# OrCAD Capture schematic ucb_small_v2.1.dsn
size C; title: NCREPT Small UCB; rev: 2.1; company: University of Arkansas (NCREPT); note: 700 W. Research Center Blvd; note: Fayetteville, AR 72701
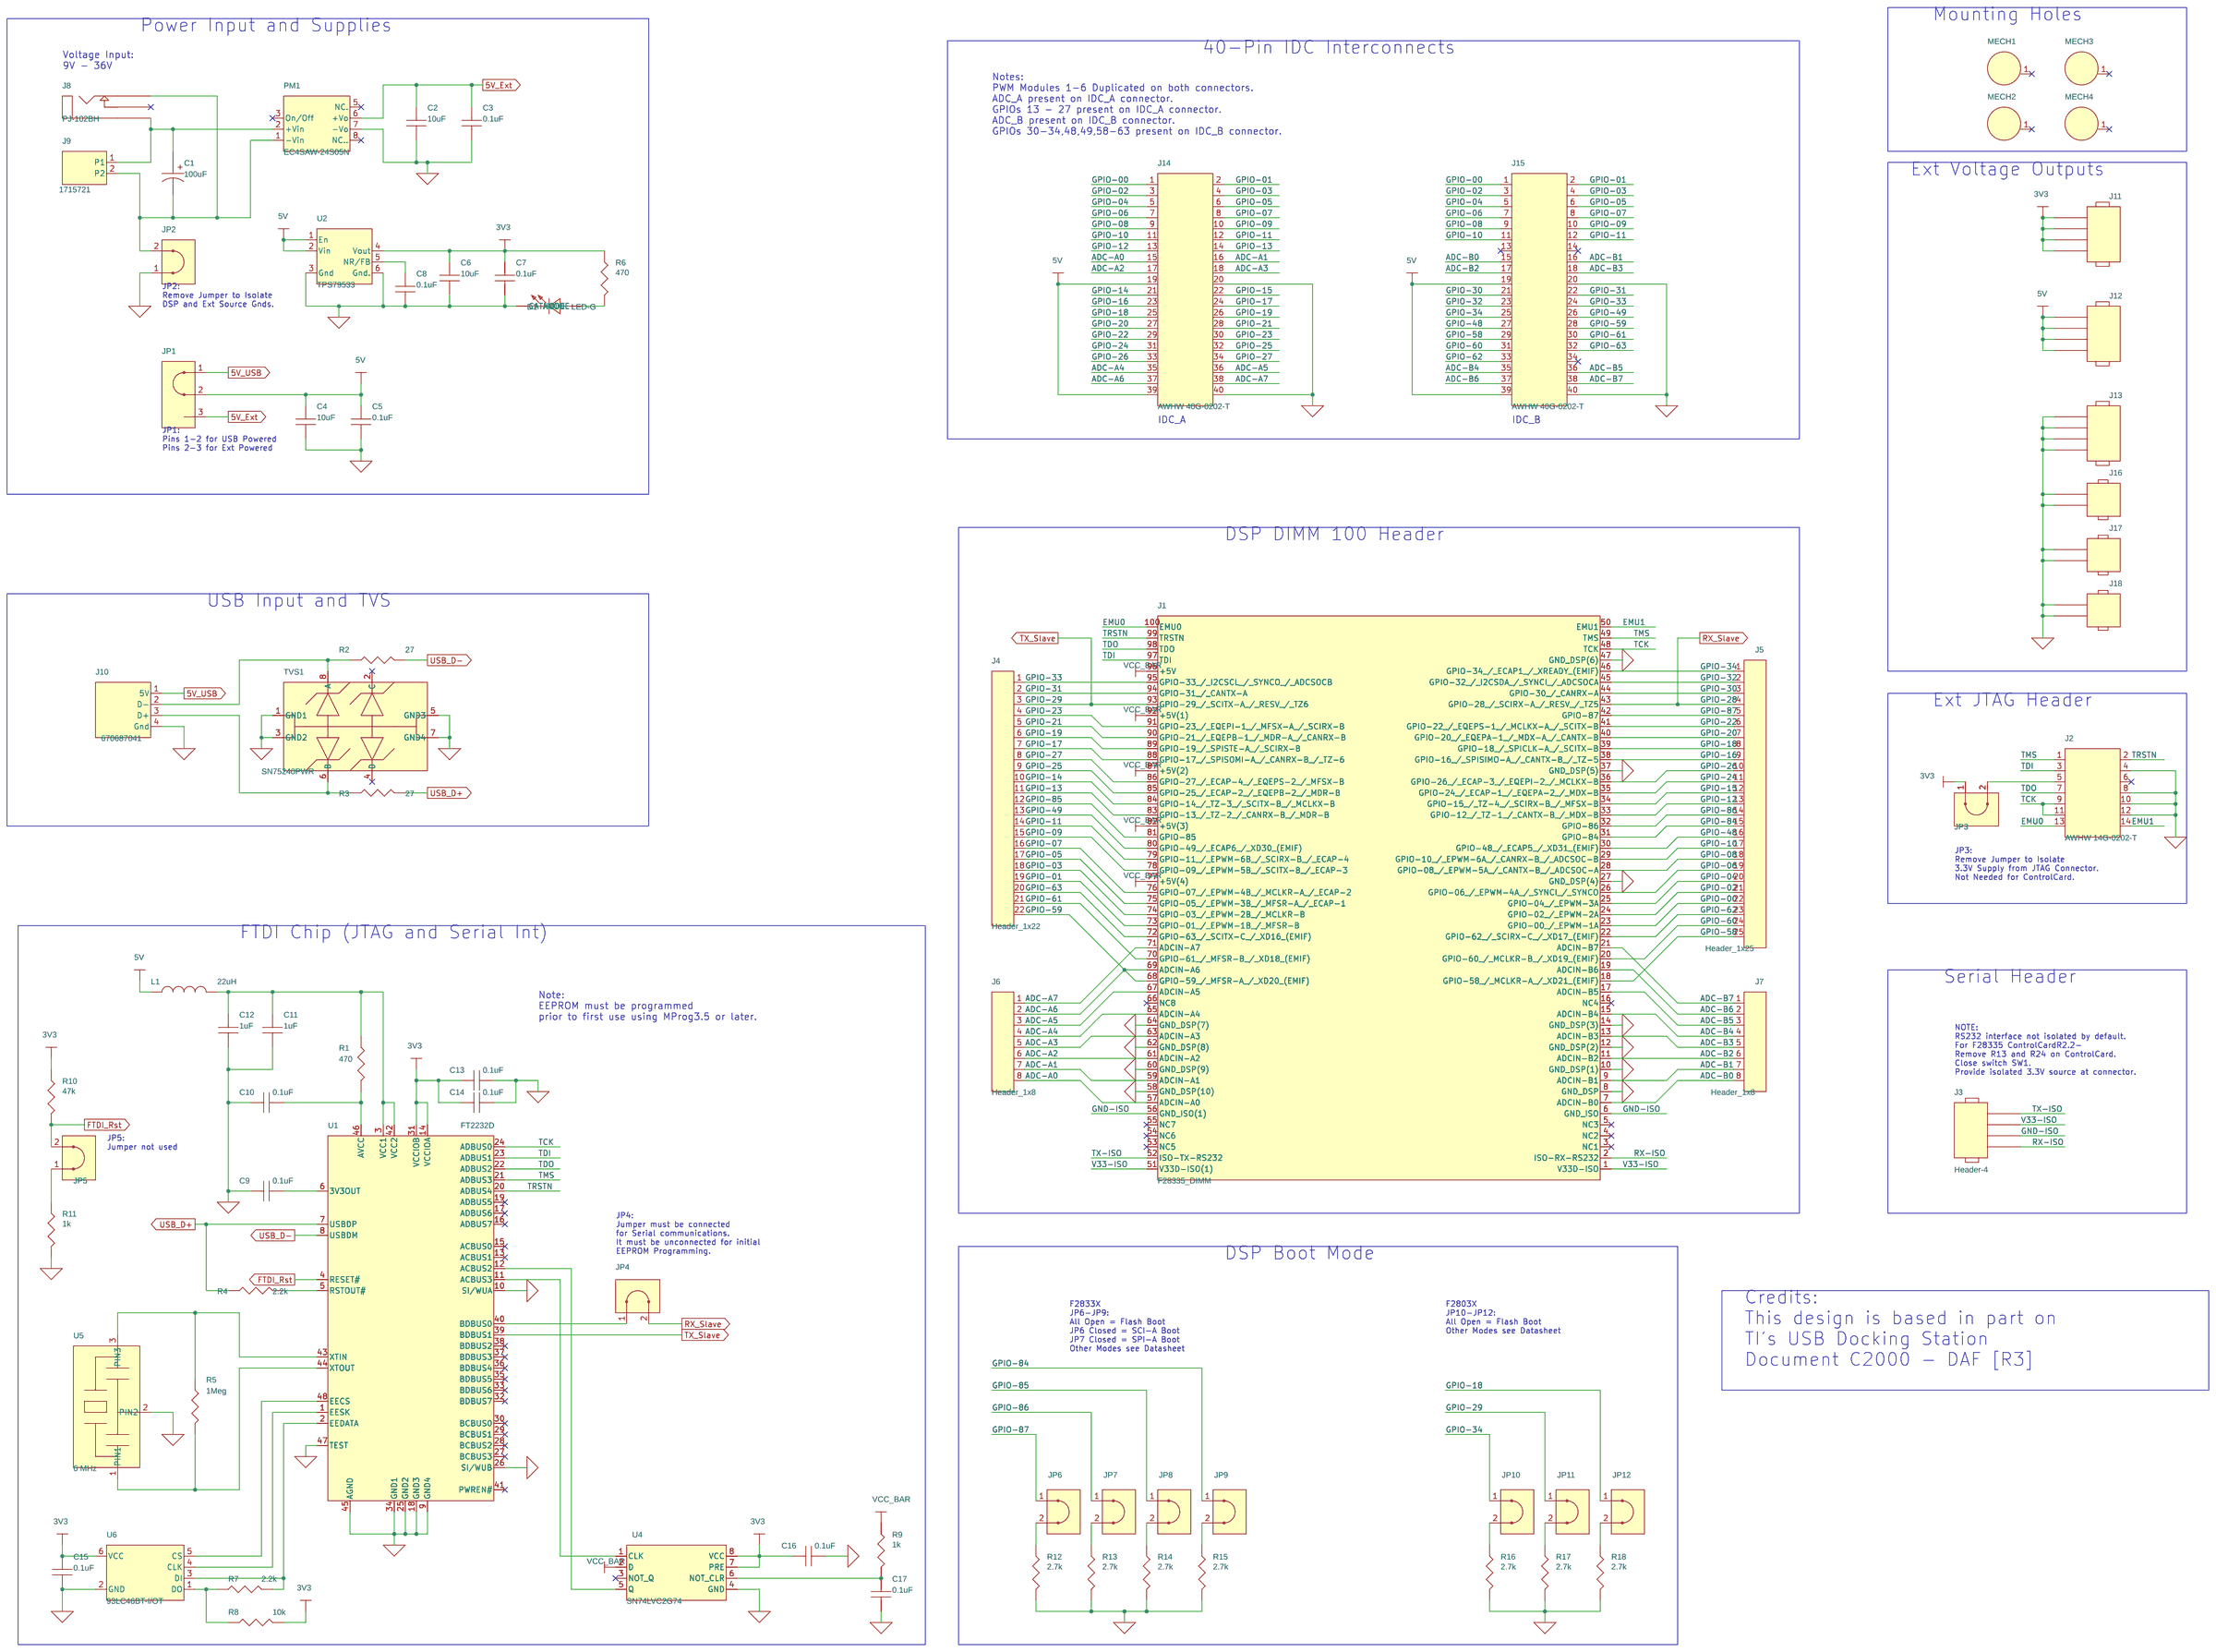
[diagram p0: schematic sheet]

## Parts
C1  100uF  [UVZ1H101MPD]
C2  10uF  [C_1206]
C3  0.1uF  [C_0603]
C4  10uF  [C_1206]
C5  0.1uF  [C_0603]
C6  10uF  [C_1206]
C7  0.1uF  [C_0603]
C8  0.1uF  [C_0603]
C9  0.1uF  [C_0603]
C10  0.1uF  [C_0603]
C11  1uF  [C_0603]
C12  1uF  [C_0603]
C13  0.1uF  [C_0603]
C14  0.1uF  [C_0603]
C15  0.1uF  [C_0603]
C16  0.1uF  [C_0603]
C17  0.1uF  [C_0603]
D1  LED-G  [LED_0805-GREEN]
J1  F28335_DIMM  [5390213-1]
J2  AWHW 14G-0202-T  [14-IDC-M]
J3  Header-4  [H_1x4]
J4  Header_1x22  [H_1X22]
J5  Header_1x25  [H_1X25]
J6  Header_1x8  [H_1X8]
J7  Header_1x8  [H_1X8]
J8  PJ-102BH  [DC-PWR_JACK]
J9  1715721  [1715721]
J10  670687041  [USB-B_TH]
J11  Header-4  [H_1x4]
J12  Header-4  [H_1x4]
J13  Header-4  [H_1x4]
J14  AWHW 40G-0202-T  [40-IDC-M_MNT]
J15  AWHW 40G-0202-T  [40-IDC-M_MNT]
J16  Header-2  [H_1x2]
J17  Header-2  [H_1x2]
J18  Header-2  [H_1x2]
JP1  JP3  [J_1X3]
JP2  JP2  [J_1X2]
JP3  JP2  [J_1X2]
JP4  JP2  [J_1X2]
JP5  JP2  [J_1X2]
JP6  JP2  [J_1X2]
JP7  JP2  [J_1X2]
JP8  JP2  [J_1X2]
JP9  JP2  [J_1X2]
JP10  JP2  [J_1X2]
JP11  JP2  [J_1X2]
JP12  JP2  [J_1X2]
L1  22uH  [L_0805]
MECH1  Mech_Hole  [4-40_SCREW]
MECH2  Mech_Hole  [4-40_SCREW]
MECH3  Mech_Hole  [4-40_SCREW]
MECH4  Mech_Hole  [4-40_SCREW]
PM1  EC4SAW-24S05N  [SIP-8]
R1  470  [R_0805]
R2  27  [R_0805]
R3  27  [R_0805]
R4  2.2k  [R_0805]
R5  1Meg  [R_0805]
R6  470  [R_0805]
R7  2.2k  [R_0805]
R8  10k  [R_0805]
R9  1k  [R_0805]
R10  47k  [R_0805]
R11  1k  [R_0805]
R12  2.7k  [R_0805]
R13  2.7k  [R_0805]
R14  2.7k  [R_0805]
R15  2.7k  [R_0805]
R16  2.7k  [R_0805]
R17  2.7k  [R_0805]
R18  2.7k  [R_0805]
TVS1  SN75240PWR  [8-TSSOP]
U1  FT2232D  [LQFP-48]
U2  TPS79533  [SOT-223-6]
U4  SN74LVC2G74  [8-VSSOP]
U5  6 MHz  [CSTCR]
U6  93LC46BT-I/OT  [SOT-23-6]

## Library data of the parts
C1 = CAP_P: Electrolytic Capacitor (50V/100uF); Manufacturer: Nichicon; Part_Number: TMP-145; Voltage: 50V; Datasheet: Nicicon-e-uvz-880014.pdf
C2 C4 C6 = CAP_NP: 10µF ±20% 35V X7R MLCC; Manufacturer: TDK; Manufacturer_Part_Number: C3216X7R1V106M160AC; Part_Number: TMP-2; Tolerance: 20%; Voltage: 35V; Datasheet: TDK-mlcc_commercial_general_en.pdf
C3 C5 C7-C10 C13-C17 = CAP_NP: 0.1µF ±10% 50V X7R MLCC; Manufacturer: TDK; Manufacturer_Part_Number: C1608X7R1H104K080AA; Part_Number: TMP-1; Tolerance: 10%; Voltage: 50V; Datasheet: TDK-mlcc_commercial_general_en.pdf
C11 C12 = CAP_NP: 1µF ±10% 35V X7R MLCC; Manufacturer: TDK; Manufacturer_Part_Number: C1608X7R1V105K080AC; Part_Number: TMP-8; Tolerance: 10%; Voltage: 35V; Datasheet: TDK-mlcc_commercial_general_en.pdf
D1 = LED: LED, 0805, Green, VF= 2.2V; Manufacturer: OSRAM; Manufacturer_Part_Number: LG R971-KN-1; Part_Number: TMP-132; STEP_Model: LED_0805-Green.stp; Datasheet: OSRAM-LGR971-CHIPLED-0805-318376.pdf
J1 = F28335_DIMM: DIMM 100 connector for TI F28335 DSP; Manufacturer: AMP; Part_Number: TMP-170; STEP_Model: c-5390213-01-b-3d.stp; Datasheet: AMP-NG_CD_5390213_B2-667800.pdf
J2 = Header_2x7: 14-POS Header, Shrouded, 0.100", TH; Manufacturer: Assmann; Part_Number: TMP-124; STEP_Model: HDB-14.stp; User_Field1: SBH11-PBPC-D07-ST-BK; Datasheet: Assmann-AWHW-xxG-0x02-T.pdf
J3 J11-J13 = HEADER_4: Male, TH, Straight, 4-Pos, 0.1" Pitch; Manufacturer: Various; Manufacturer_Part_Number: PRT-00116; Part_Number: TMP-25; STEP_Model: Pin Header 1x4 TH Pitch 2.54mm.stp
J4 = Header_1x22: Male, TH, Straight, 22-Pos, 0.1" Pitch; Manufacturer: Various; Manufacturer_Part_Number: PRT-00116; Part_Number: TMP-168; STEP_Model: mill-max-800-10-022-10-002000.stp; Datasheet: Sullins-z RzCzzzSzzN-RC, ST,11635-B.pdf
J5 = Header_1x25: Male, TH, Straight, 25-Pos, 0.1" Pitch; Manufacturer: Various; Manufacturer_Part_Number: PRT-00116; Part_Number: TMP-169; STEP_Model: mill-max-800-10-025-10-002000.stp; Datasheet: Sullins-z RzCzzzSzzN-RC, ST,11635-B.pdf
J6 J7 = Header_1x8: Male, TH, Straight, 8-Pos, 0.1" Pitch; Manufacturer: Various; Manufacturer_Part_Number: PRT-00116; Part_Number: TMP-167; STEP_Model: Pin Header 1x8 TH Pitch 2.54mm.stp; Datasheet: Sullins-z RzCzzzSzzN-RC, ST,11635-B.pdf
J8 = DC-Jack_3: DC Power Jack, 2.5mm Center Pin, TH; Manufacturer: CUI; Part_Number: TMP-150; STEP_Model: pj-102bh.stp; Datasheet: CUI-PJ-102BH-524153.pdf
J9 = Connector-2: PCB Terminal Block, 2-position, 90 degrees, 5.08mm; Manufacturer: Phoenix Contact; Part_Number: TMP-111; Rating: 17.5A; STEP_Model: 1715721.stp; Voltage: 400V; Datasheet: PhoenixContact-1715734.pdf
J10 = USB-B: USB - B Receptacle Connector 4-POS, TH, Right Angle; Manufacturer: Molex; Part_Number: TMP-161; STEP_Model: USB-0670687041.stp; Datasheet: Molex-670687041_sd.pdf
J14 J15 = Header_2x20: 40-POS Header, Shrouded, 0.100", TH, Male w/ Mounting; Manufacturer: Assmann; Part_Number: TMP-162; STEP_Model: HDB-40.stp; Datasheet: Assmann-AWHW-xxG-0x02-T.pdf
J16-J18 = HEADER_2: Male, TH, Straight, 2-Pos, 0.1" Pitch; Manufacturer: Various; Manufacturer_Part_Number: PRT-00116; Part_Number: TMP-101; STEP_Model: Pin Header 1x2 TH Pitch 2.54mm.stp
JP1 = JP3: Male, TH, Straight, 3-Pos, 0.1" Pitch; Manufacturer: Various; Manufacturer_Part_Number: PRT-00116; Part_Number: TMP-136
JP2-JP12 = JP2: Male, TH, Straight, 2-Pos, 0.1" Pitch; Manufacturer: Various; Manufacturer_Part_Number: PRT-00116; Part_Number: TMP-135
L1 = Ind: 22uH,13mA, Fixed Inductor, ±30%; Manufacturer: Murata; Manufacturer_Part_Number: LQM21FN220N00L; Part_Number: TMP-159; Rating: 13mA; Tolerance: 30.00%; Datasheet: Murata-o05e.pdf
MECH1-MECH4 = Mech_Hole: Mounting Hole for 4-40 Screw, 0.125"; Part_Number: TMP-103
PM1 = EC4SA: Isolated DC/DC Converters 6 Watt, 9-36 Vin, 5 Vout; Manufacturer: Cincon; Part_Number: TMP-118; STEP_Model: PwrMod-SIP8.stp; Datasheet: CINCON-EC4SAW V10-557886.pdf
R1 R6 = R-Standard: 470 Ohm, 1%, 0805; Manufacturer: KOA Speer; Manufacturer_Part_Number: RK73H2ATTD4700F; Part_Number: TMP-172; Rating: 0.125W; Tolerance: 1%; Datasheet: KOA-RK73H-5715.pdf
R2 R3 = R-Standard: 27 Ohm, 1%, 0805; Manufacturer: KOA Speer; Manufacturer_Part_Number: RK73H2ATTD27R0F; Part_Number: TMP-171; Rating: 0.125W; Tolerance: 1%; Datasheet: KOA-RK73H-5715.pdf
R4 R7 = R-Standard: 2.2k Ohm, 1%, 0805; Manufacturer: KOA Speer; Manufacturer_Part_Number: RK73H2ATTD2201F; Part_Number: TMP-173; Rating: 0.125W; Tolerance: 1%; Datasheet: KOA-RK73H-5715.pdf
R5 = R-Standard: 1Meg Ohm, 1%, 0805; Manufacturer: KOA Speer; Manufacturer_Part_Number: RK73H2ATTD1004F; Part_Number: TMP-175; Rating: 0.125W; Tolerance: 1%; Datasheet: KOA-RK73H-5715.pdf
R8 = R-Standard: 10k Ohm, 1%, 0805; Manufacturer: KOA Speer; Manufacturer_Part_Number: RK73H2ATTD1002F; Part_Number: TMP-68; Rating: 0.125W; Tolerance: 1%; Datasheet: KOA-RK73H-5715.pdf
R9 R11 = R-Standard: 1k Ohm, 1%, 0805; Manufacturer: KOA Speer; Manufacturer_Part_Number: RK73H2ATTD1001F; Part_Number: TMP-48; Rating: 0.125W; Tolerance: 1%; Datasheet: KOA-RK73H-5715.pdf
R10 = R-Standard: 47k Ohm, 1%, 0805; Manufacturer: KOA Speer; Manufacturer_Part_Number: RK73H2ATTD4702F; Part_Number: TMP-140; Rating: 0.125W; Tolerance: 1%; Datasheet: KOA-RK73H-5715.pdf
R12-R18 = R-Standard: 2.7k Ohm, 1%, 0805; Manufacturer: KOA Speer; Manufacturer_Part_Number: RK73H2ATTD2701F; Part_Number: TMP-174; Rating: 0.125W; Tolerance: 1%; Datasheet: KOA-RK73H-5715.pdf
TVS1 = SN75240: TVS Diode Arrays Dual USB Port; Manufacturer: TI; Part_Number: TMP-166; STEP_Model: TSSOP65P640X120-8N.stp; Datasheet: TI-sn75240-557324.pdf
U1 = FT2232D: USB Interface IC USB to Dual UART/ FIFO/SPI/JTAG/I2C (TI); Manufacturer: FTDI; Manufacturer_Part_Number: FT2232D-REEL; Part_Number: TMP-158; STEP_Model: LQFP-48.stp; Datasheet: FTDI-DS_FT2232D-17197.pdf
U2 = TPS795: LDO Voltage Reg, 3.3V, 500mA, 2%; Manufacturer: TI; Manufacturer_Part_Number: TPS79533DCQR; Part_Number: TMP-155; STEP_Model: SOT-223-6.stp; Datasheet: TI-tps795-706600.pdf
U4 = SN74LVC2G74: Flip Flops Single Pos Edge Trig; Manufacturer: TI; Part_Number: TMP-157; STEP_Model: VSSOP_SOP50P310X90-8N.stp; Datasheet: TI-sn74lvc2g74-556136.pdf
U5 = CSTCR_G: 6MHz Ceramic Resonator Built in Capacitor 15pF ±0.2%; Manufacturer: Murata; Manufacturer_Part_Number: CSTCR6M00G53Z-R0; Part_Number: TMP-160; Datasheet: Murata-p16e.pdf
U6 = 93LC46BT: EEPROM 64x16, 1kb, Serial, 3-Wire, Microwire; Manufacturer: Microchip; Part_Number: TMP-156; STEP_Model: SOT23-6.stp; Datasheet: Microchip-21749d-6388.pdf

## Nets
3V3: C6.1 C7.1 C13.1 C14.1 C15.1 C16.1 J11.1 J11.2 J11.3 J11.4 JP3.1 R6.1 R8.2 R9.1 R10.1 U1.14(VCCIOA) U1.31(VCCIOB) U2.4(Vout) U4.2(D) U4.7(PRE) U4.8(VCC) U6.6(VCC)
5V: C4.1 C5.1 J1.77(+5V(4)) J1.82(+5V(3)) J1.87(+5V(2)) J1.92(+5V(1)) J1.96(+5V) J12.1 J12.2 J12.3 J12.4 J14.19 J14.39 J15.19 J15.39 JP1.2 L1.1 U2.1(En) U2.2(Vin)
5V_Ext: C2.1 C3.1 JP1.3 PM1.6(+Vo)
5V_USB: J10.1(5V) JP1.1
GND-ISO: J1.6(GND_ISO) J1.56(GND_ISO(1)) J3.3
GND_SIGNAL: C2.2 C3.2 C4.2 C5.2 C6.2 C7.2 C8.2 C9.1 C10.1 C11.2 C12.2 C13.2 C14.2 C15.2 C16.2 C17.2 D1.1(CATHODE) J1.8(GND_DSP) J1.10(GND_DSP(1)) J1.12(GND_DSP(2)) J1.14(GND_DSP(3)) J1.27(GND_DSP(4)) J1.37(GND_DSP(5)) J1.47(GND_DSP(6)) J1.58(GND_DSP(10)) J1.60(GND_DSP(9)) J1.62(GND_DSP(8)) J1.64(GND_DSP(7)) J2.4 J2.8 J2.10 J2.12 J10.4(Gnd) J13.1 J13.2 J13.3 J13.4 J14.20 J14.40 J15.20 J15.40 J16.1 J16.2 J17.1 J17.2 J18.1 J18.2 JP2.1 PM1.7(-Vo) R11.2 R12.2 R13.2 R14.2 R15.2 R16.2 R17.2 R18.2 TVS1.1(GND1) TVS1.3(GND2) TVS1.5(GND3) TVS1.7(GND4) U1.9(GND4) U1.10(SI/WUA) U1.18(GND3) U1.25(GND2) U1.26(SI/WUB) U1.34(GND1) U1.45(AGND) U1.47(TEST) U2.3(Gnd) U2.6(Gnd.) U4.4(GND) U5.2(PIN2) U6.2(GND)
V33-ISO: J1.1(V33D-ISO) J1.51(V33D-ISO(1)) J3.2
ADC-A0: J1.57(ADCIN-A0) J6.8 J14.15
ADC-A1: J1.59(ADCIN-A1) J6.7 J14.16
ADC-A2: J1.61(ADCIN-A2) J6.6 J14.17
ADC-A3: J1.63(ADCIN-A3) J6.5 J14.18
ADC-A4: J1.65(ADCIN-A4) J6.4 J14.35
ADC-A5: J1.67(ADCIN-A5) J6.3 J14.36
ADC-A6: J1.69(ADCIN-A6) J6.2 J14.37
ADC-A7: J1.71(ADCIN-A7) J6.1 J14.38
ADC-B0: J1.7(ADCIN-B0) J7.8 J15.15
ADC-B1: J1.9(ADCIN-B1) J7.7 J15.16
ADC-B2: J1.11(ADCIN-B2) J7.6 J15.17
ADC-B3: J1.13(ADCIN-B3) J7.5 J15.18
ADC-B4: J1.15(ADCIN-B4) J7.4 J15.35
ADC-B5: J1.17(ADCIN-B5) J7.3 J15.36
ADC-B6: J1.19(ADCIN-B6) J7.2 J15.37
ADC-B7: J1.21(ADCIN-B7) J7.1 J15.38
EMU0: J1.100(EMU0) J2.13
EMU1: J1.50(EMU1) J2.14
FTDI_Rst: JP5.2 R10.2 U1.4(RESET#)
GPIO-00: J1.23(GPIO-00_/_EPWM-1A) J5.22 J14.1 J15.1
GPIO-01: J1.73(GPIO-01_/_EPWM-1B_/_MFSR-B) J4.19 J14.2 J15.2
GPIO-02: J1.24(GPIO-02_/_EPWM-2A) J5.21 J14.3 J15.3
GPIO-03: J1.74(GPIO-03_/_EPWM-2B_/_MCLKR-B) J4.18 J14.4 J15.4
GPIO-04: J1.25(GPIO-04_/_EPWM-3A) J5.20 J14.5 J15.5
GPIO-05: J1.75(GPIO-05_/_EPWM-3B_/_MFSR-A_/_ECAP-1) J4.17 J14.6 J15.6
GPIO-06: J1.26(GPIO-06_/_EPWM-4A_/_SYNCI_/_SYNCO) J5.19 J14.7 J15.7
GPIO-07: J1.76(GPIO-07_/_EPWM-4B_/_MCLKR-A_/_ECAP-2) J4.16 J14.8 J15.8
GPIO-08: J1.28(GPIO-08_/_EPWM-5A_/_CANTX-B_/_ADCSOC-A) J5.18 J14.9 J15.9
GPIO-09: J1.78(GPIO-09_/_EPWM-5B_/_SCITX-B_/_ECAP-3) J4.15 J14.10 J15.10
GPIO-10: J1.29(GPIO-10_/_EPWM-6A_/_CANRX-B_/_ADCSOC-B) J5.17 J14.11 J15.11
GPIO-11: J1.79(GPIO-11_/_EPWM-6B_/_SCIRX-B_/_ECAP-4) J4.14 J14.12 J15.12
GPIO-12: J1.33(GPIO-12_/_TZ-1_/_CANTX-B_/_MDX-B) J5.13 J14.13
GPIO-13: J1.83(GPIO-13_/_TZ-2_/_CANRX-B_/_MDR-B) J4.11 J14.14
GPIO-14: J1.84(GPIO-14_/_TZ-3_/_SCITX-B_/_MCLKX-B) J4.10 J14.21
GPIO-15: J1.34(GPIO-15_/_TZ-4_/_SCIRX-B_/_MFSX-B) J5.12 J14.22
GPIO-16: J1.38(GPIO-16_/_SPISIMO-A_/_CANTX-B_/_TZ-5) J5.9 J14.23
GPIO-17: J1.88(GPIO-17_/_SPISOMI-A_/_CANRX-B_/_TZ-6) J4.7 J14.24
GPIO-18: J1.39(GPIO-18_/_SPICLK-A_/_SCITX-B) J5.8 J14.25 JP12.1
GPIO-19: J1.89(GPIO-19_/_SPISTE-A_/_SCIRX-B) J4.6 J14.26
GPIO-20: J1.40(GPIO-20_/_EQEPA-1_/_MDX-A_/_CANTX-B) J5.7 J14.27
GPIO-21: J1.90(GPIO-21_/_EQEPB-1_/_MDR-A_/_CANRX-B) J4.5 J14.28
GPIO-22: J1.41(GPIO-22_/_EQEPS-1_/_MCLKX-A_/_SCITX-B) J5.6 J14.29
GPIO-23: J1.91(GPIO-23_/_EQEPI-1_/_MFSX-A_/_SCIRX-B) J4.4 J14.30
GPIO-24: J1.35(GPIO-24_/_ECAP-1_/_EQEPA-2_/_MDX-B) J5.11 J14.31
GPIO-25: J1.85(GPIO-25_/_ECAP-2_/_EQEPB-2_/_MDR-B) J4.9 J14.32
GPIO-26: J1.36(GPIO-26_/_ECAP-3_/_EQEPI-2_/_MCLKX-B) J5.10 J14.33
GPIO-27: J1.86(GPIO-27_/_ECAP-4_/_EQEPS-2_/_MFSX-B) J4.8 J14.34
GPIO-30: J1.44(GPIO-30_/_CANRX-A) J5.3 J15.21
GPIO-31: J1.94(GPIO-31_/_CANTX-A) J4.2 J15.22
GPIO-32: J1.45(GPIO-32_/_I2CSDA_/_SYNCI_/_ADCSOCA) J5.2 J15.23
GPIO-33: J1.95(GPIO-33_/_I2CSCL_/_SYNCO_/_ADCSOCB) J4.1 J15.24
GPIO-34: J1.46(GPIO-34_/_ECAP1_/_XREADY_(EMIF)) J5.1 J15.25 JP10.1
GPIO-48: J1.30(GPIO-48_/_ECAP5_/_XD31_(EMIF)) J5.16 J15.27
GPIO-49: J1.80(GPIO-49_/_ECAP6_/_XD30_(EMIF)) J4.13 J15.26
GPIO-58: J1.18(GPIO-58_/_MCLKR-A_/_XD21_(EMIF)) J5.25 J15.29
GPIO-59: J1.68(GPIO-59_/_MFSR-A_/_XD20_(EMIF)) J4.22 J15.28
GPIO-60: J1.20(GPIO-60_/_MCLKR-B_/_XD19_(EMIF)) J5.24 J15.31
GPIO-61: J1.70(GPIO-61_/_MFSR-B_/_XD18_(EMIF)) J4.21 J15.30
GPIO-62: J1.22(GPIO-62_/_SCIRX-C_/_XD17_(EMIF)) J5.23 J15.33
GPIO-63: J1.72(GPIO-63_/_SCITX-C_/_XD16_(EMIF)) J4.20 J15.32
GPIO-84: J1.31(GPIO-84) J5.15 JP9.1
GPIO-85: J1.81(GPIO-85) J4.12 JP8.1
GPIO-86: J1.32(GPIO-86) J5.14 JP7.1
GPIO-87: J1.42(GPIO-87) J5.5 JP6.1
RX-ISO: J1.2(ISO-RX-RS232) J3.4
RX_Slave: J1.43(GPIO-28_/_SCIRX-A_/_RESV_/_TZ5) J5.4 JP4.2
TCK: J1.48(TCK) J2.9 J2.11 U1.24(ADBUS0)
TDI: J1.97(TDI) J2.3 U1.23(ADBUS1)
TDO: J1.98(TDO) J2.7 U1.22(ADBUS2)
TMS: J1.49(TMS) J2.1 U1.21(ADBUS3)
TRSTN: J1.99(TRSTN) J2.2 U1.20(ADBUS4)
TX-ISO: J1.52(ISO-TX-RS232) J3.1
TX_Slave: J1.93(GPIO-29_/_SCITX-A_/_RESV_/_TZ6) J4.3 JP11.1 U1.39(BDBUS1)
USB_D+: R3.2 R4.1 U1.7(USBDP)
USB_D-: R2.2 U1.8(USBDM)
N12195: C1.1 J8.1 J9.1(P1) PM1.2(+Vin)
N12272: C1.2 J8.2 J9.2(P2) JP2.2 PM1.1(-Vin)
N18531: C8.1 U2.5(NR/FB)
N22439: J10.2(D-) R2.1 TVS1.8(A)
N22457: J10.3(D+) R3.1 TVS1.6(B)
N23366: R4.2 U1.5(RSTOUT#)
N23404: R5.2 U1.44(XTOUT) U5.1(PIN1)
N23422: R5.1 U1.43(XTIN) U5.3(PIN3)
N24717: C9.2 U1.6(3V3OUT)
N25180: D1.2(ANODE) R6.2
N25279: C11.1 C12.1 L1.2 R1.1 U1.3(VCC1) U1.42(VCC2)
N25286: C10.2 R1.2 U1.46(AVCC)
N28281: J2.5 JP3.2
N29672: U1.11(ACBUS3) U4.1(CLK)
N29684: U1.12(ACBUS2) U4.5(Q)
N29790: JP4.1 U1.40(BDBUS0)
N34054: R7.1 R8.1 U6.1(DO)
N34072: R7.2 U1.2(EEDATA) U6.3(DI)
N34220: U1.1(EESK) U6.4(CLK)
N34232: U1.48(EECS) U6.5(CS)
N41056: C17.1 R9.2 U4.6(NOT_CLR)
N43288: JP5.1 R11.1
N46408: JP10.2 R16.1
N46412: JP11.2 R17.1
N46416: JP12.2 R18.1
N46420: JP6.2 R12.1
N46424: JP7.2 R13.1
N46428: JP8.2 R14.1
N46432: JP9.2 R15.1

Not connected (* = marked no-connect by the designer): J1 3(NC1)* 4(NC2)* 5(NC3)* 16(NC4)* 53(NC5)* 54(NC6)* 55(NC7)* 66(NC8)*; J2 6*; J8 3*; J15 13* 14* 34*; MECH1 1*; MECH2 1*; MECH3 1*; MECH4 1*; PM1 3(On/Off)* 5(NC.)* 8(NC..)*; TVS1 2(C)* 4(D)*; U1 13(ACBUS1)* 15(ACBUS0)* 16(ADBUS7)* 17(ADBUS6)* 19(ADBUS5)* 27(BCBUS3)* 28(BCBUS2)* 29(BCBUS1)* 30(BCBUS0)* 32(BDBUS7)* 33(BDBUS6)* 35(BDBUS5)* 36(BDBUS4)* 37(BDBUS3)* 38(BDBUS2)* 41(PWREN#)*; U4 3(NOT_Q)*

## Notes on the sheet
- Mounting Holes
- Power Input and Supplies
- Voltage Input:
  9V - 36V
- 40-Pin IDC Interconnects
- Notes:
  PWM Modules 1-6 Duplicated on both connectors.
  ADC_A present on IDC_A connector.
  GPIOs 13 - 27 present on IDC_A connector.
  ADC_B present on IDC_B connector.
  GPIOs 30-34,48,49,58-63 present on IDC_B connector.
- Ext Voltage Outputs
- JP2:
  Remove Jumper to Isolate
  DSP and Ext Source Gnds.
- IDC_A
- IDC_B
- JP1:
  Pins 1-2 for USB Powered
  Pins 2-3 for Ext Powered
- DSP DIMM 100 Header
- USB Input and TVS
- Ext JTAG Header
- JP3:
  Remove Jumper to Isolate
  3.3V Supply from JTAG Connector.
  Not Needed for ControlCard.
- FTDI Chip (JTAG and Serial Int)
- Serial Header
- Note:
  EEPROM must be programmed
  prior to first use using MProg3.5 or later.
- NOTE:
  RS232 interface not isolated by default.
  For F28335 ControlCardR2.2-
  Remove R13 and R24 on ControlCard.
  Close switch SW1.
  Provide isolated 3.3V source at connector.
- JP5:
  Jumper not used
- JP4:
  Jumper must be connected
  for Serial communications.
  It must be unconnected for initial
  EEPROM Programming.
- DSP Boot Mode
- Credits:
  This design is based in part on
  TI's USB Docking Station
  Document C2000 - DAF [R3]
- F2833X
  JP6-JP9:
  All Open = Flash Boot
  JP6 Closed = SCI-A Boot
  JP7 Closed = SPI-A Boot
  Other Modes see Datasheet
- F2803X
  JP10-JP12:
  All Open = Flash Boot
  Other Modes see Datasheet
